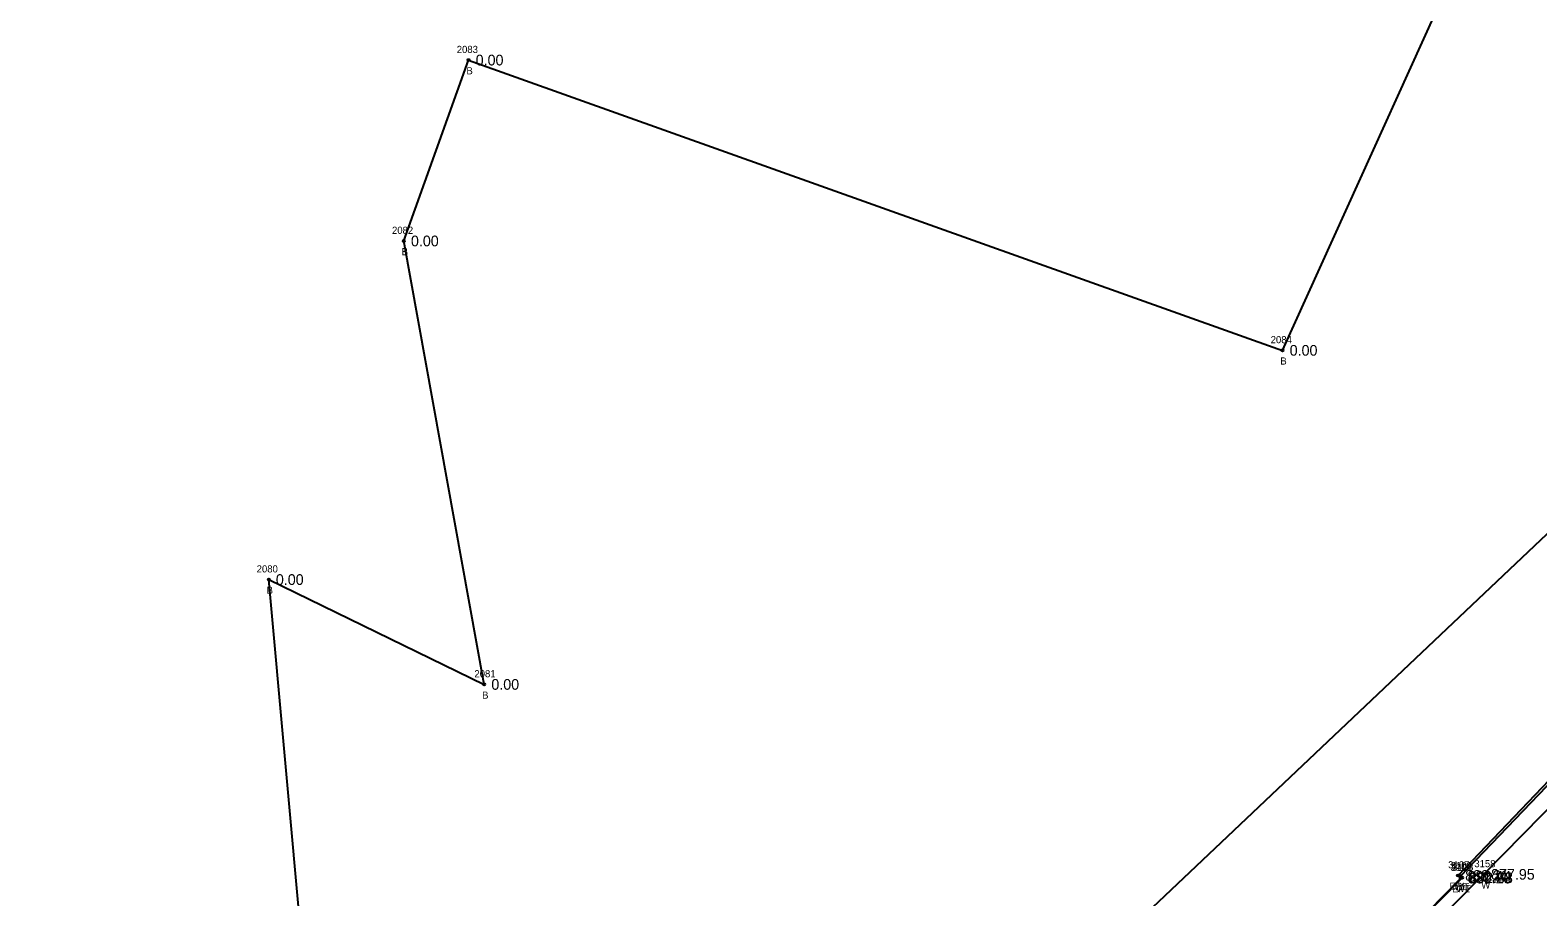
# Model space of a CAD drawing. Extents: x 1622501 to 1626664, y 1117816 to 1121579.
# Drawn here: x 1623518 to 1623729.9, y 1119124.7 to 1119246.3 of the extents above; entities that cross this region are included whole.
import ezdxf

# ---------------------------------------------------------------- set-up
doc = ezdxf.new("R2010")
doc.units = 0
for name, color, linetype in [('RD_EX_Bldg', 7, 'Continuous'), ('RD_EX_Bldg_txCode', 7, 'Continuous'), ('RD_EX_BldgApp', 7, 'Continuous'), ('RD_EX_DR_Pipe', 7, 'Continuous'), ('RD_EX_Misc', 7, 'Continuous'), ('RD_EX_Misc_txCode', 7, 'Continuous'), ('RD_EX_Road', 7, 'Continuous'), ('RD_EX_Road_txCode', 7, 'Continuous'), ('RD_EX_TX_Bldg_ELEV', 7, 'Continuous'), ('RD_EX_TX_Misc_ELEV', 7, 'Continuous'), ('RD_EX_TX_Road_ELEV', 7, 'Continuous'), ('RD_SMD_Locator', 7, 'Continuous')]:
    doc.layers.add(name, color=color, linetype=linetype)

msp = doc.modelspace()

# ---------------------------------------------------------------- linework, layer by layer
at = {"layer": 'RD_EX_Bldg'}
msp.add_lwpolyline([(1623201.46, 1118937.29), (1623247.83, 1118918.76), (1623241.45, 1118902.79), (1623389.45, 1118843.65), (1623513.15, 1119089.64), (1623560.94, 1119066.03), (1623551.58, 1119169.2), (1623581.86, 1119154.48), (1623570.56, 1119216.75), (1623579.66, 1119242.15), (1623694.05, 1119201.39), (1623724.63, 1119268.84), (1623626.64, 1119464.02), (1623435.76, 1119529.1), (1623352.72, 1119285.56), (1623272.86, 1119308.21), (1623231.87, 1119163.66), (1623284.27, 1119148.8), (1623201.46, 1118937.29)], dxfattribs=at)
at = {"layer": 'RD_EX_BldgApp'}
msp.add_lwpolyline([(1623611.88, 1119041.63), (1623617.16, 1119021.48), (1623649.67, 1119054.03), (1623681.05, 1119086.16), (1623722.35, 1119127.81), (1623757.94, 1119164), (1623796.61, 1119203.22), (1623812.89, 1119220.06), (1623805.76, 1119227.09), (1623820.9, 1119266.21)], dxfattribs=at)
at = {"layer": 'RD_EX_DR_Pipe'}
msp.add_line((1623590.49, 1119042.52), (1623772.69, 1119214.88), dxfattribs=at)
at = {"layer": 'RD_EX_Misc'}
msp.add_lwpolyline([(1623612.49, 1119041.84), (1623617.78, 1119023.46), (1623650.79, 1119057.14), (1623650.63, 1119057.3), (1623678.34, 1119085.34), (1623703.43, 1119110.78), (1623703.19, 1119111), (1623719.28, 1119127.33), (1623719.05, 1119127.54), (1623738.85, 1119148.21), (1623776.59, 1119185.95), (1623789.62, 1119199.19), (1623809.92, 1119220.22), (1623803.28, 1119226.62), (1623818.74, 1119266.26)], dxfattribs=at)
at = {"layer": 'RD_EX_Road'}
msp.add_lwpolyline([(1623613.19, 1119042.02), (1623617.82, 1119023.74), (1623650.67, 1119057.11), (1623650.47, 1119057.34), (1623678.18, 1119085.43), (1623703.28, 1119110.83), (1623703.12, 1119110.99), (1623719.09, 1119127.28), (1623718.71, 1119127.65), (1623738.45, 1119148.27), (1623776.49, 1119186.3), (1623774.18, 1119207.71)], dxfattribs=at)
at = {"layer": 'RD_SMD_Locator'}
for centre in [(1623579.66, 1119242.15), (1623570.56, 1119216.75), (1623694.05, 1119201.39), (1623551.58, 1119169.2), (1623581.86, 1119154.48), (1623718.71, 1119127.65), (1623719.05, 1119127.54), (1623719.09, 1119127.28), (1623719.28, 1119127.33), (1623722.35, 1119127.81)]:
    msp.add_circle(centre, 0.15, dxfattribs=at)

# ---------------------------------------------------------------- texts
at = {"layer": 'RD_EX_Bldg_txCode'}
for s, p in [('2083', (1623578, 1119243.15)), ('B', (1623579.36, 1119240.15)), ('2082', (1623568.9, 1119217.75)), ('B', (1623570.26, 1119214.75)), ('2084', (1623692.38, 1119202.39)), ('B', (1623693.74, 1119199.39)), ('2080', (1623549.88, 1119170.2)), ('B', (1623551.28, 1119167.2)), ('2081', (1623580.48, 1119155.48)), ('B', (1623581.56, 1119152.48))]:
    msp.add_text(s, height=1, dxfattribs=at).set_placement(p)
at = {"layer": 'RD_EX_Misc_txCode'}
for s, p in [('3109', (1623717.67, 1119128.54)), ('3108', (1623717.89, 1119128.33)), ('3158', (1623721, 1119128.81)), ('WT', (1623718.19, 1119125.54)), ('WT', (1623718.42, 1119125.33)), ('W', (1623721.98, 1119125.81))]:
    msp.add_text(s, height=1, dxfattribs=at).set_placement(p)
at = {"layer": 'RD_EX_Road_txCode'}
for s, p in [('3107', (1623717.32, 1119128.65)), ('3106', (1623717.68, 1119128.28)), ('EPL', (1623717.5, 1119125.65)), ('EPL', (1623717.88, 1119125.28))]:
    msp.add_text(s, height=1, dxfattribs=at).set_placement(p)
at = {"layer": 'RD_EX_TX_Bldg_ELEV'}
for p in [(1623580.66, 1119241.4), (1623571.56, 1119216), (1623695.05, 1119200.64), (1623552.58, 1119168.45), (1623582.86, 1119153.73)]:
    msp.add_text('0.00', height=1.5, dxfattribs=at).set_placement(p)
at = {"layer": 'RD_EX_TX_Misc_ELEV'}
for s, p in [('892.44', (1623720.05, 1119126.79)), ('892.68', (1623720.28, 1119126.58)), ('877.95', (1623723.35, 1119127.06))]:
    msp.add_text(s, height=1.5, dxfattribs=at).set_placement(p)
at = {"layer": 'RD_EX_TX_Road_ELEV'}
for s, p in [('889.21', (1623719.71, 1119126.9)), ('889.23', (1623720.09, 1119126.53))]:
    msp.add_text(s, height=1.5, dxfattribs=at).set_placement(p)

doc.saveas('drawing.dxf')
